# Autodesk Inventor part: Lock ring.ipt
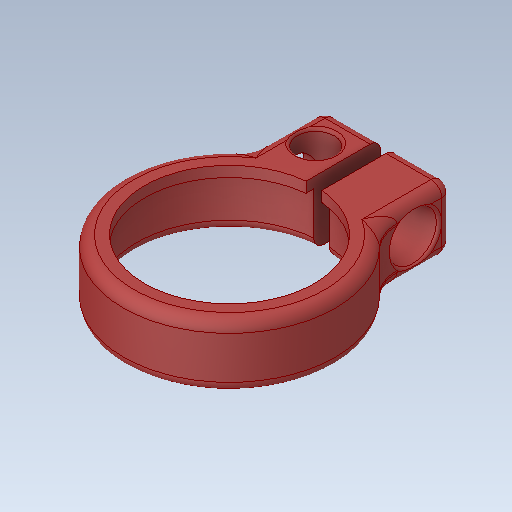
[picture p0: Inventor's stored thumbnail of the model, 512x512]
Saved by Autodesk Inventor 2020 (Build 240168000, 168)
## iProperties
Created: 2017-10
Part Number: Lock ring.ipt
Material: Ogólny
Document SubType Name: Modeling
Designer: Tomasz
Density: 1 g/cm^3
Appearance: Domyślna
Sending System: SolidWorks 2017
Last Author: Tomasz
Last Saved: 2017-10-01
Author: Tomasz
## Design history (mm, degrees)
feature "Lock ring.ipt"
node "Bryła1"
